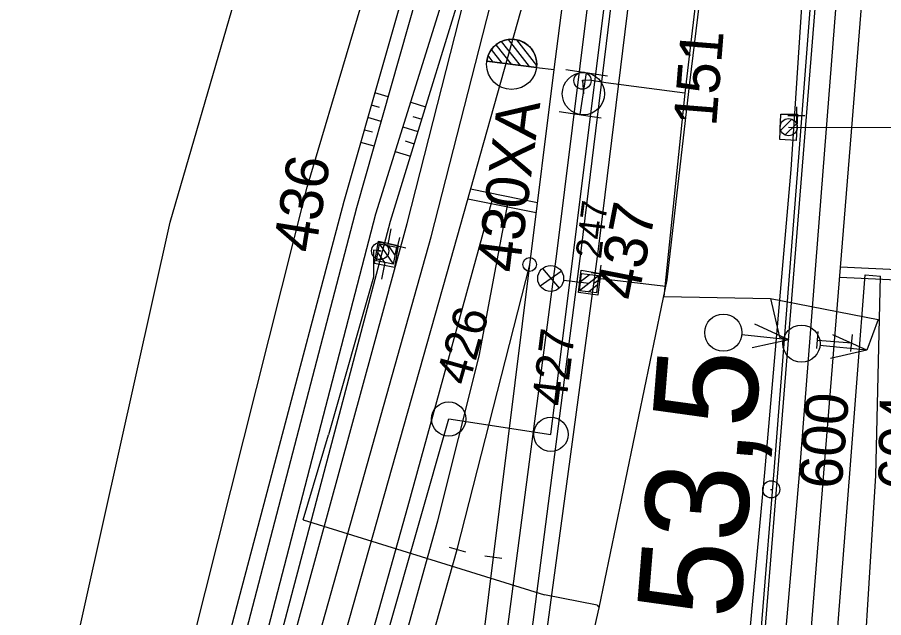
# Model space of a CAD drawing. Extents: x -598638 to -597933, y -1164002 to -1161904.
# Drawn here: x -598296.5 to -598246.1, y -1163313.4 to -1163278.4 of the extents above; entities that cross this region are included whole.
import ezdxf

# ---------------------------------------------------------------- set-up
doc = ezdxf.new("R2010")
doc.units = 0
for name, color, linetype in [('Vrstva 1', 7, 'Continuous'), ('Vrstva 11', 7, 'Continuous'), ('Vrstva 12', 7, 'Continuous'), ('Vrstva 2', 7, 'Continuous'), ('Vrstva 25', 7, 'Continuous'), ('Vrstva 26', 7, 'Continuous'), ('Vrstva 28', 7, 'Continuous'), ('Vrstva 3', 7, 'Continuous'), ('Vrstva 35', 7, 'Continuous'), ('Vrstva 4', 7, 'Continuous'), ('Vrstva 43', 7, 'Continuous'), ('Vrstva 44', 7, 'Continuous'), ('Vrstva 48', 7, 'Continuous'), ('Vrstva 49', 7, 'Continuous'), ('Vrstva 51', 7, 'Continuous'), ('Vrstva 7', 7, 'Continuous')]:
    doc.layers.add(name, color=color, linetype=linetype)

msp = doc.modelspace()

# ---------------------------------------------------------------- linework, layer by layer
at = {"layer": 'Vrstva 1'}
for points in [[(-598250.9, -1163321.936), (-598249.53, -1163304.978), (-598248.914, -1163297.297), (-598247.877, -1163284.361), (-598246.649, -1163269.02)], [(-598290.948, -1163362.176), (-598285.982, -1163344.65), (-598282.717, -1163333.052), (-598281.168, -1163327.552), (-598279.885, -1163323.01), (-598271.302, -1163292.589), (-598266.808, -1163276.648)], [(-598265.253, -1163281.456), (-598264.695, -1163277.054)], [(-598268.795, -1163309.856), (-598266.673, -1163292.83), (-598265.253, -1163281.456)], [(-598270.9, -1163309.421), (-598266.673, -1163292.83)], [(-598286.211, -1163363.553), (-598281.229, -1163345.959), (-598277.392, -1163332.383), (-598276.288, -1163328.478), (-598275.12, -1163324.336), (-598270.9, -1163309.421)], [(-598269.379, -1163314.559), (-598268.795, -1163309.856)]]:
    msp.add_lwpolyline(points, dxfattribs=at)
at = {"layer": 'Vrstva 11'}
for p, q in [((-598252.051, -1163284.994), (-598251.405, -1163284.348)), ((-598251.791, -1163285.264), (-598251.136, -1163284.609)), ((-598274.937, -1163291.719), (-598274.749, -1163290.727)), ((-598274.628, -1163292.761), (-598275.404, -1163291.62)), ((-598274.529, -1163292.241), (-598274.883, -1163291.719)), ((-598275.13, -1163292.69), (-598275.522, -1163292.112)), ((-598275.122, -1163292.687), (-598275.311, -1163293.673)), ((-598263.774, -1163294.336), (-598262.668, -1163293.461)), ((-598263.713, -1163293.809), (-598263.195, -1163293.4)), ((-598263.251, -1163294.4), (-598262.726, -1163293.985))]:
    msp.add_line(p, q, dxfattribs=at)
for points in [[(-598251.59, -1163284.81), (-598236.23, -1163284.83)], [(-598275.615, -1163292.597), (-598275.427, -1163291.615), (-598274.445, -1163291.803), (-598274.633, -1163292.785), (-598275.615, -1163292.597)], [(-598263.659, -1163293.345), (-598262.665, -1163293.461), (-598262.781, -1163294.455), (-598263.775, -1163294.339), (-598263.659, -1163293.345)]]:
    msp.add_lwpolyline(points, dxfattribs=at)
for points in [[(-598275.615, -1163292.597), (-598275.427, -1163291.615), (-598274.445, -1163291.803), (-598274.633, -1163292.785)], [(-598263.659, -1163293.345), (-598262.665, -1163293.461), (-598262.781, -1163294.455), (-598263.775, -1163294.339)]]:
    msp.add_lwpolyline(points, close=True, dxfattribs=at)
msp.add_circle((-598251.59, -1163284.81), 0.5, dxfattribs=at)
at = {"layer": 'Vrstva 12'}
for points in [[(-598252.11, -1163285.52), (-598252.04, -1163284.06), (-598251.07, -1163284.06), (-598251.15, -1163285.58), (-598252.11, -1163285.52)], [(-598274.35, -1163291.71), (-598274.56, -1163292.98), (-598275.72, -1163292.76), (-598275.48, -1163291.46), (-598274.35, -1163291.71)], [(-598263.84, -1163294.45), (-598263.68, -1163293.14), (-598262.56, -1163293.33), (-598262.71, -1163294.6), (-598263.84, -1163294.45)]]:
    msp.add_lwpolyline(points, dxfattribs=at)
at = {"layer": 'Vrstva 2'}
for p, q in [((-598267.222, -1163281.213), (-598268.313, -1163279.811)), ((-598266.696, -1163281.279), (-598267.923, -1163279.702)), ((-598266.268, -1163281.218), (-598267.434, -1163279.719)), ((-598268.275, -1163281.081), (-598268.898, -1163280.279)), ((-598267.749, -1163281.146), (-598268.636, -1163280.007)), ((-598268.802, -1163281.015), (-598269.094, -1163280.639)), ((-598266.274, -1163281.331), (-598269.179, -1163280.968)), ((-598269.179, -1163280.968), (-598266.274, -1163281.331)), ((-598266.274, -1163281.331), (-598266.274, -1163281.331)), ((-598266.273, -1163281.332), (-598265.253, -1163281.456)), ((-598271.381, -1163309.285), (-598270.419, -1163309.557)), ((-598269.291, -1163309.794), (-598268.299, -1163309.918))]:
    msp.add_line(p, q, dxfattribs=at)
for points in [[(-598268.795, -1163309.856), (-598266.673, -1163292.83), (-598265.253, -1163281.456)], [(-598270.9, -1163309.421), (-598266.673, -1163292.83)]]:
    msp.add_lwpolyline(points, dxfattribs=at)
for centre, radius in [((-598267.734, -1163281.147), 1.462), ((-598266.681, -1163292.81), 0.4)]:
    msp.add_circle(centre, radius, dxfattribs=at)
msp.add_arc((-598267.727, -1163281.15), 1.464, 352.9032, 172.8641, dxfattribs=at)
at = {"layer": 'Vrstva 25'}
for p, q in [((-598263.65, -1163282.1), (-598263.55, -1163282.1)), ((-598275.442, -1163292.025), (-598275.342, -1163292.025)), ((-598266.078, -1163294.051), (-598264.839, -1163293.192)), ((-598265.939, -1163293.045), (-598264.964, -1163294.195)), ((-598264.709, -1163293.718), (-598263.22, -1163293.9))]:
    msp.add_line(p, q, dxfattribs=at)
for centre, radius in [((-598263.604, -1163282.099), 0.5), ((-598275.392, -1163292.025), 0.5), ((-598265.457, -1163293.624), 0.754)]:
    msp.add_circle(centre, radius, dxfattribs=at)
at = {"layer": 'Vrstva 26'}
for points in [[(-598273.816, -1163355.578), (-598271.677, -1163346.374), (-598270.289, -1163341.485), (-598268.518, -1163336.06), (-598265.457, -1163325.157), (-598262.629, -1163312.811), (-598258.667, -1163293.697), (-598257.35, -1163282.225), (-598255.678, -1163268.505), (-598254.603, -1163254.848), (-598253.891, -1163243.597), (-598253.428, -1163235.813)], [(-598275.392, -1163292.025), (-598275.782, -1163291.982), (-598275.774, -1163293.544), (-598278.398, -1163302.728)], [(-598258.751, -1163294.103), (-598262.556, -1163293.644), (-598262.901, -1163293.901)], [(-598279.877, -1163307.689), (-598278.398, -1163302.728)], [(-598279.877, -1163307.689), (-598265.808, -1163312.057)], [(-598262.747, -1163312.654), (-598265.808, -1163312.057)], [(-598262.747, -1163312.654), (-598262.629, -1163312.811)]]:
    msp.add_lwpolyline(points, dxfattribs=at)
at = {"layer": 'Vrstva 28'}
for points in [[(-598253.43, -1163232.8), (-598254.31, -1163244.16), (-598254.67, -1163249.79), (-598255.78, -1163266.99), (-598257.63, -1163282.82), (-598258.86, -1163294.68), (-598252.64, -1163294.8), (-598246.37, -1163296.02), (-598247.03, -1163297.8)], [(-598257.63, -1163282.82), (-598262.24, -1163282.22), (-598263.19, -1163282.07), (-598263.6, -1163282.1), (-598263.55, -1163282.86)], [(-598252.64, -1163294.8), (-598252.12, -1163297.05), (-598251.58, -1163297.2)]]:
    msp.add_lwpolyline(points, dxfattribs=at)
at = {"layer": 'Vrstva 3'}
for p, q in [((-598264.582, -1163281.456), (-598262.146, -1163281.828)), ((-598263.736, -1163284.078), (-598263.364, -1163281.642)), ((-598264.954, -1163283.892), (-598262.518, -1163284.264)), ((-598251.58, -1163297.2), (-598253.565, -1163296.294)), ((-598251.58, -1163297.2), (-598254.324, -1163296.906)), ((-598249.952, -1163297.713), (-598249.87, -1163296.717)), ((-598247.03, -1163297.8), (-598249.024, -1163296.914)), ((-598247.958, -1163297.877), (-598247.876, -1163296.881)), ((-598251.58, -1163297.2), (-598253.712, -1163297.666)), ((-598249.911, -1163297.215), (-598247.917, -1163297.379)), ((-598247.03, -1163297.8), (-598249.777, -1163297.535)), ((-598247.03, -1163297.8), (-598249.157, -1163298.288))]:
    msp.add_line(p, q, dxfattribs=at)
for centre, radius in [((-598263.547, -1163282.859), 1.232), ((-598255.394, -1163296.781), 1.084), ((-598250.842, -1163297.424), 1.084)]:
    msp.add_circle(centre, radius, dxfattribs=at)
at = {"layer": 'Vrstva 35'}
msp.add_lwpolyline([(-598252.64, -1163294.8), (-598246.37, -1163296.02)], dxfattribs=at)
at = {"layer": 'Vrstva 4'}
for points in [[(-598398.167, -1163553.239), (-598376.487, -1163515.918), (-598348.795, -1163467.979), (-598339.716, -1163452.202), (-598323.266, -1163423.236), (-598308.372, -1163396.471), (-598302.715, -1163384.123), (-598298.324, -1163372.137), (-598289.593, -1163344.221), (-598282.967, -1163321.229), (-598274.797, -1163290.285), (-598269.404, -1163272.781), (-598266.519, -1163258.633), (-598263.896, -1163241.651), (-598261.185, -1163218.05), (-598260.503, -1163217.001), (-598259.092, -1163201.513), (-598258.163, -1163186.176), (-598256.557, -1163141.317), (-598256.485, -1163129.008), (-598255.651, -1163108.451), (-598254.34, -1163087.718), (-598253.319, -1163075.132)], [(-598307.376, -1163503.64), (-598306.256, -1163500.72), (-598304.527, -1163496.743), (-598299.478, -1163486.144), (-598290.117, -1163465.204), (-598280.795, -1163442.724), (-598274.814, -1163425.66), (-598269.09, -1163405.616), (-598262.907, -1163380.487), (-598260.225, -1163366.071), (-598256.638, -1163342.661), (-598254.612, -1163322.432), (-598252.977, -1163304.928), (-598251.437, -1163287.268), (-598250.068, -1163266.224), (-598248.818, -1163245.446), (-598248.467, -1163214.545), (-598248.623, -1163173.63), (-598248.072, -1163131.254), (-598247.596, -1163128.349)], [(-598388.69, -1163572.819), (-598382.701, -1163561.089), (-598361.383, -1163524.292), (-598334.6, -1163477.579), (-598308.353, -1163432.12), (-598292.471, -1163404.257), (-598285.937, -1163390.16), (-598281.631, -1163378.652), (-598277.216, -1163365.008), (-598272.579, -1163348.284), (-598269.387, -1163336.75), (-598267.113, -1163324.869), (-598262.674, -1163291.919), (-598258.642, -1163259.137), (-598254.182, -1163220.99), (-598251.647, -1163201.068), (-598250.766, -1163187.503), (-598249.671, -1163144.519), (-598248.922, -1163130.776), (-598248.69, -1163130.313)]]:
    msp.add_lwpolyline(points, dxfattribs=at)
at = {"layer": 'Vrstva 43'}
for centre in [(-598271.397, -1163301.809), (-598265.446, -1163302.712)]:
    msp.add_circle(centre, 1, dxfattribs=at)
at = {"layer": 'Vrstva 44'}
for points in [[(-598295.758, -1163493.483), (-598278.118, -1163452.874), (-598264.209, -1163410.565), (-598254.468, -1163367.19), (-598248.62, -1163321.577), (-598253.497, -1163320.887), (-598249.615, -1163272.581), (-598247.635, -1163222.481), (-598247.486, -1163176.779), (-598247.442, -1163130.148), (-598244.014, -1163084.171), (-598235.33, -1163037.762), (-598224.817, -1163002.559), (-598219.379, -1163002.169), (-598206.652, -1162968.487), (-598191.401, -1162936.053), (-598173.754, -1162904.506), (-598155.689, -1162873.083), (-598136.14, -1162838.446), (-598116.776, -1162804.197)], [(-598280.199, -1163332.648), (-598271.397, -1163301.809), (-598265.446, -1163302.712), (-598259.208, -1163252.741), (-598251.788, -1163176.385), (-598250.383, -1163130.296), (-598247.948, -1163083.491), (-598241.007, -1163044.927)]]:
    msp.add_lwpolyline(points, dxfattribs=at)
at = {"layer": 'Vrstva 48'}
for p, q in [((-598274.917, -1163283.035), (-598275.696, -1163282.813)), ((-598273.615, -1163283.36), (-598272.746, -1163283.628)), ((-598275.433, -1163283.667), (-598275.901, -1163283.534)), ((-598275.326, -1163284.477), (-598276.106, -1163284.255)), ((-598273.49, -1163284.184), (-598272.967, -1163284.345)), ((-598274.063, -1163284.792), (-598273.188, -1163285.062)), ((-598275.843, -1163285.11), (-598276.312, -1163284.976)), ((-598275.736, -1163285.92), (-598276.517, -1163285.698)), ((-598273.935, -1163285.616), (-598273.408, -1163285.778)), ((-598274.51, -1163286.224), (-598273.629, -1163286.495))]:
    msp.add_line(p, q, dxfattribs=at)
at = {"layer": 'Vrstva 49'}
for points in [[(-598299.445, -1163361.058), (-598297.068, -1163359.059), (-598293.068, -1163343.621), (-598287.79, -1163320.649), (-598279.637, -1163288.312), (-598274.636, -1163271.434), (-598271.523, -1163257.595), (-598269.283, -1163241.904), (-598267.104, -1163218.072), (-598264.127, -1163206.783), (-598263.144, -1163204.971), (-598260.62, -1163202.843), (-598259.578, -1163186.018), (-598258.253, -1163141.176), (-598259.192, -1163127.718), (-598260.075, -1163119.279), (-598261.182, -1163115.692), (-598261.349, -1163113.122), (-598258.894, -1163101.538), (-598255.65, -1163087.809), (-598254.518, -1163075.132), (-598252.098, -1163061.479), (-598247.841, -1163044.835)], [(-598309.446, -1163203.262), (-598316.229, -1163215.539), (-598313.873, -1163217.741), (-598321.933, -1163233.799), (-598326.308, -1163254.29), (-598324.871, -1163281.374), (-598324.668, -1163290.005), (-598320.258, -1163307.426), (-598325.507, -1163312.636), (-598323.584, -1163327.934), (-598325.353, -1163339.082), (-598298.967, -1163343.623), (-598293.544, -1163316.86), (-598287.625, -1163290.34), (-598280.443, -1163265.616), (-598276.989, -1163242.095), (-598274.987, -1163221.639), (-598274.592, -1163211.298), (-598290.163, -1163206.434), (-598302.523, -1163205.338), (-598306.323, -1163207.572)], [(-598350.075, -1163469.161), (-598350.962, -1163468.642), (-598341.128, -1163451.449), (-598324.91, -1163422.41), (-598309.936, -1163395.461), (-598304.358, -1163383.215), (-598300.139, -1163371.399), (-598292.224, -1163343.911), (-598285.916, -1163320.98), (-598277.492, -1163289.124), (-598272.642, -1163272.084), (-598269.771, -1163257.778), (-598267.544, -1163241.285), (-598265.728, -1163218.657), (-598264.511, -1163217.412), (-598261.185, -1163218.05)], [(-598350.962, -1163468.642), (-598340.803, -1163451.583), (-598324.406, -1163422.648), (-598309.58, -1163395.796), (-598303.887, -1163383.446), (-598299.666, -1163371.582), (-598291.401, -1163343.859), (-598285.02, -1163321.209), (-598276.751, -1163289.495), (-598271.739, -1163271.843), (-598268.729, -1163258.218), (-598266.553, -1163241.22), (-598264.463, -1163218.64)], [(-598350.075, -1163469.161), (-598340.252, -1163451.87), (-598323.84, -1163422.849), (-598308.915, -1163396.15), (-598303.181, -1163383.749), (-598299.003, -1163371.924), (-598290.374, -1163343.997), (-598283.872, -1163321.586), (-598275.648, -1163289.867), (-598270.185, -1163272.379), (-598267.391, -1163258.396), (-598265.172, -1163241.341), (-598262.635, -1163218.663), (-598264.463, -1163218.64)]]:
    msp.add_lwpolyline(points, dxfattribs=at)
at = {"layer": 'Vrstva 51'}
for points in [[(-598397.431, -1163553.318), (-598375.745, -1163515.943), (-598348.098, -1163468.333), (-598322.38, -1163423.533), (-598307.542, -1163396.818), (-598301.86, -1163384.541), (-598297.285, -1163372.341), (-598293.283, -1163359.379), (-598288.845, -1163344.448), (-598282.25, -1163321.235), (-598273.825, -1163290.423), (-598265.756, -1163258.778), (-598260.545, -1163219.203), (-598259.744, -1163217.171), (-598258.57, -1163201.891), (-598257.659, -1163186.255), (-598256.038, -1163142.193), (-598255.793, -1163128.623), (-598255.065, -1163108.27), (-598253.781, -1163088.998), (-598252.62, -1163075.466)], [(-598396.078, -1163554.151), (-598374.443, -1163516.599), (-598347.031, -1163469.014), (-598321.218, -1163424.261), (-598306.253, -1163397.723), (-598300.608, -1163385.153), (-598295.814, -1163372.93), (-598291.849, -1163359.988), (-598287.46, -1163344.41), (-598281.154, -1163322.32), (-598272.412, -1163291.197), (-598264.229, -1163259.135), (-598258.972, -1163219.27), (-598257.327, -1163201.644), (-598256.369, -1163186.491), (-598254.79, -1163142.649), (-598254.397, -1163128.629), (-598253.571, -1163108.317), (-598252.585, -1163090.153), (-598250.983, -1163076.012)], [(-598384.985, -1163560.822), (-598363.176, -1163523.063), (-598335.955, -1163475.581), (-598310.179, -1163431.066), (-598295.149, -1163404.135), (-598288.465, -1163389.583), (-598283.96, -1163377.815), (-598279.772, -1163364.473), (-598275.196, -1163348.33), (-598271.933, -1163336.198), (-598269.31, -1163324.265), (-598265.084, -1163292.029), (-598261.053, -1163259.678), (-598256.104, -1163220.296), (-598254.426, -1163201.671), (-598253.667, -1163187.936), (-598252.018, -1163143.494), (-598251.534, -1163128.863), (-598250.791, -1163108.998), (-598250.069, -1163094.383), (-598248.218, -1163076.729)], [(-598305.922, -1163504.285), (-598297.335, -1163487.137), (-598287.92, -1163465.981), (-598279.035, -1163443.103), (-598273.208, -1163425.978), (-598267.2, -1163406.108), (-598261.011, -1163380.887), (-598258.166, -1163366.304), (-598254.569, -1163343.143), (-598252.435, -1163322.084), (-598250.965, -1163305.051), (-598249.488, -1163286.133), (-598247.962, -1163266.793), (-598246.718, -1163245.404), (-598246.637, -1163214.417), (-598246.633, -1163173.748), (-598246.347, -1163129.422), (-598245.484, -1163112.939), (-598244.076, -1163096.672), (-598241.475, -1163076.865)], [(-598298.888, -1163486.593), (-598289.113, -1163465.583), (-598279.905, -1163442.964), (-598274.107, -1163425.699), (-598268.268, -1163405.757), (-598262.238, -1163380.596), (-598259.701, -1163366.461), (-598255.999, -1163342.847), (-598253.859, -1163322.319), (-598252.407, -1163304.609), (-598250.982, -1163286.31), (-598249.458, -1163266.6), (-598248.128, -1163245.447), (-598247.963, -1163214.31), (-598248.01, -1163173.778), (-598247.475, -1163130.652), (-598247.596, -1163128.349), (-598246.685, -1163112.866), (-598245.177, -1163096.514), (-598242.921, -1163076.624)], [(-598389.422, -1163572.47), (-598383.242, -1163561.018), (-598361.933, -1163523.985), (-598335.337, -1163477.363), (-598309.065, -1163431.797), (-598293.626, -1163404.644), (-598286.924, -1163390.082), (-598282.523, -1163378.361), (-598278.252, -1163364.663), (-598273.758, -1163348.557), (-598270.372, -1163336.656), (-598267.892, -1163324.623), (-598263.657, -1163291.858), (-598259.724, -1163259.57), (-598255.007, -1163220.516), (-598252.865, -1163201.196), (-598252.034, -1163187.935), (-598250.643, -1163143.798), (-598250.023, -1163129.244), (-598249.184, -1163109.078), (-598248.423, -1163094.475), (-598246.693, -1163077.089)], [(-598405.752, -1163584.856), (-598406.565, -1163584.53), (-598399.621, -1163567.58), (-598392.991, -1163554.623), (-598370.643, -1163515.908), (-598344.594, -1163470.689), (-598318.975, -1163426.348), (-598303.98, -1163399.626), (-598297.883, -1163386.424), (-598293.238, -1163374.41), (-598289.078, -1163361.082), (-598284.443, -1163344.622), (-598278.418, -1163323.499), (-598273.781, -1163306.93), (-598268.859, -1163289.076)], [(-598405.752, -1163584.856), (-598398.056, -1163568.29), (-598390.909, -1163555.148), (-598369.148, -1163517.525), (-598342.954, -1163471.89), (-598317.093, -1163427.101), (-598302.088, -1163400.435), (-598295.928, -1163387.037), (-598291.26, -1163374.845), (-598287.219, -1163361.857), (-598282.441, -1163344.932), (-598276.551, -1163323.978), (-598272.024, -1163307.744), (-598269.633, -1163298.161), (-598267.957, -1163289.279), (-598268.859, -1163289.076)], [(-598249.328, -1163321.623), (-598248.023, -1163304.979), (-598247.126, -1163293.411), (-598246.23, -1163293.485)], [(-598249.328, -1163321.623), (-598247.542, -1163321.734), (-598246.515, -1163305.107), (-598246.23, -1163293.485)]]:
    msp.add_lwpolyline(points, dxfattribs=at)
at = {"layer": 'Vrstva 7'}
for p, q in [((-598251.141, -1163283.622), (-598251.141, -1163284.622)), ((-598251.641, -1163284.122), (-598250.641, -1163284.122)), ((-598270.122, -1163288.404), (-598266.219, -1163289.193)), ((-598270.285, -1163288.983), (-598266.293, -1163289.79)), ((-598274.265, -1163291.231), (-598274.501, -1163292.201)), ((-598274.868, -1163291.598), (-598273.898, -1163291.834)), ((-598262.531, -1163292.855), (-598262.673, -1163293.845)), ((-598248.565, -1163292.946), (-598244.854, -1163293.124)), ((-598263.097, -1163293.279), (-598262.107, -1163293.421)), ((-598248.613, -1163293.544), (-598244.864, -1163293.725)), ((-598252.653, -1163305.913), (-598252.553, -1163305.913))]:
    msp.add_line(p, q, dxfattribs=at)
msp.add_circle((-598252.603, -1163305.913), 0.5, dxfattribs=at)

# ---------------------------------------------------------------- texts
at = {"layer": 'Vrstva 1'}
for s, rotation, p in [('600', 85.416, (-598248.513, -1163305.948)), ('604', 89.0765, (-598243.868, -1163305.969))]:
    msp.add_text(s, height=2.5, rotation=rotation, dxfattribs=at).set_placement(p)
at = {"layer": 'Vrstva 11'}
for s, rotation, p in [('151', 85.4462, (-598255.814, -1163284.81)), ('436', 80.8377, (-598279.178, -1163292.2)), ('437', 78.8305, (-598260.382, -1163294.992))]:
    msp.add_text(s, height=2.5, rotation=rotation, dxfattribs=at).set_placement(p)
at = {"layer": 'Vrstva 2'}
msp.add_text('430XA', height=2.5, rotation=82.8837, dxfattribs=at).set_placement((-598267.299, -1163293.351))
at = {"layer": 'Vrstva 25'}
msp.add_text('247', height=1.5, rotation=83.0366, dxfattribs=at).set_placement((-598262.53, -1163292.518))
at = {"layer": 'Vrstva 43'}
for s, rotation, p in [('426', 74.2441, (-598270.244, -1163299.935)), ('427', 82.8957, (-598264.582, -1163301.126))]:
    msp.add_text(s, height=2, rotation=rotation, dxfattribs=at).set_placement(p)
at = {"layer": 'Vrstva 7'}
msp.add_text('153,5', height=6, rotation=85.3812, dxfattribs=at).set_placement((-598254.828, -1163318.007))

doc.saveas('drawing.dxf')
